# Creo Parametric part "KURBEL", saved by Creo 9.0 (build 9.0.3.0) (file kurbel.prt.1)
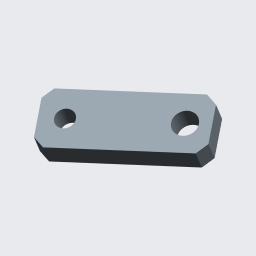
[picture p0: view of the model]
Units: millimeter Kilogram Sec (mmKs); MM, KILOGRAM, SECS
Materials in the file: STAHL

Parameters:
  WERKSTOFF = "Stahl"
  ERSTELLER = "ARINDA"
  BENENNUNG = "XXX"
  TEILETYP = "K"
  PTC_MASTER_MATERIAL = "STAHL"

Other parameters: MASSE

Created from: ARINDA_STARTTEIL.PRT

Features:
  1. coordinate system
  2. datum plane "RECHTS_Y-Z"
  3. datum plane "OBEN_X-Z"
  4. datum plane "VORNE_X-Y"
  5. datum axis
  6. datum axis
  7. datum axis
  8. datum point "PNT0"
  9. extrusion "Profil 1"
  10. hole "Bohrung 2"
  11. hole "Bohrung 3"
  12. chamfer "Fase 1"

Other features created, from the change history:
  coordinate system "CS1"
  sketch "Skizze 1"
  hole "Bohrung 1"

Other named items: GRUNDKÖRPER, HEBEL, ANTRIEBSSCHEIBE, A_X, A_Y, A_Z, CS0

Layers: 01_ACHSEN, 01_ACHSEN_STD, 01_EBENEN_STD, 01_KOORDSYS_STD, 01_KURVEN, 01_PUNKTE_STD, GEWINDE, SAMMELFLÄCHEN, VOLUMENGEOMETRIE

Surfaces: 10 plane, 2 cylinder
